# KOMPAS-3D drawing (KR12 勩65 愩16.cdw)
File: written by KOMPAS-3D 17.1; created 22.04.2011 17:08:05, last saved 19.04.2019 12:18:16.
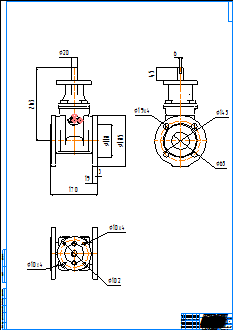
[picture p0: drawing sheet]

Title block, sheet 1: name: KR12 Ду65 Ру16; material: Внимание! Данный продукт является объектом авторского права ООО «Торговый Дом АДЛ». / Запрещается изменение, копирование, распространение / (в том числе путем копирования на другие сайты и ресурсы в Интернете) / или любое иное использование информации и объектов без предварительного / согласия правообладателя (ООО «Торговый Дом АДЛ»).; scale: 1:1; sheets: 1; organisation: ООО "Торговый дом АДЛ"; sheet format: A0; stored path: \\adlc.lan\data\АДЛ_ПКД\3D-модели\ADL production\Клиновые задвижки серии KR ГРАНАР\Клиновые задвижки KR12\KOMPAS 2D\KR12 Ду65 Ру16.cdw

Views: Спереди 4, Проекционный вид 5, Проекционный вид 6
Dimensions and other numbers on the sheet: 170; 19; 3; 185; 118; 263; 20; 102; 10; 145; 65; 45; 6; 1:1; 1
